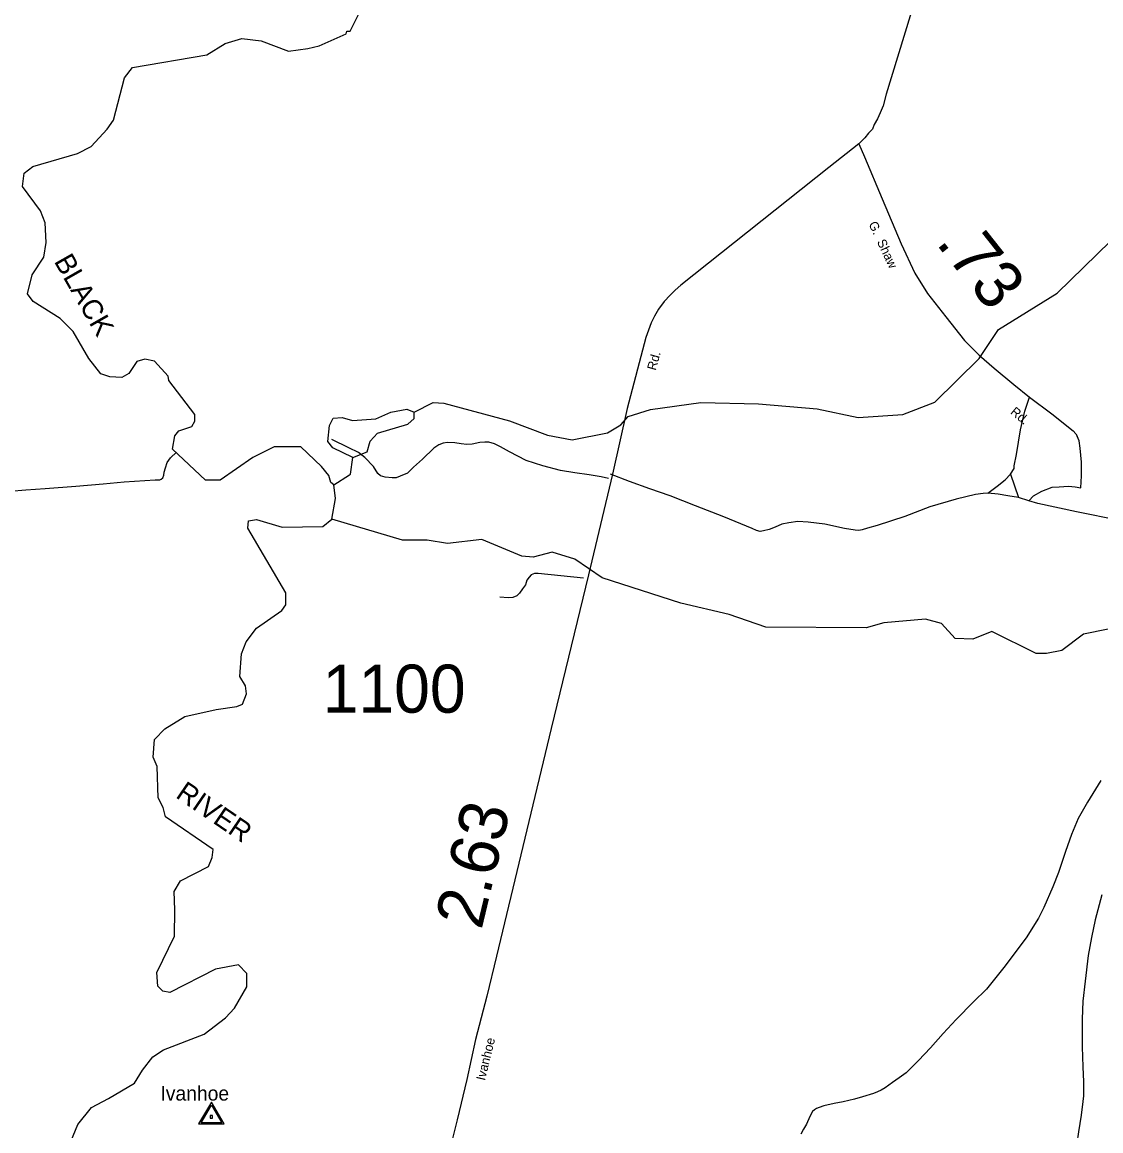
# Model space of a CAD drawing. Extents: x 2093524 to 2270757, y 289120 to 570408.
# Drawn here: x 2222555 to 2233771, y 318082 to 329610 of the extents above; entities that cross this region are included whole.
import ezdxf

# ---------------------------------------------------------------- set-up
doc = ezdxf.new("R2010")
doc.units = 0
for name, color, linetype in [('Exist Hydrographic Creek Single Shore', 7, 'Continuous'), ('Exist Hydrographic Lake Shore', 7, 'Continuous'), ('Exist Hydrographic River Shore', 7, 'Continuous'), ('Exist Hydrographic River Shore Label', 7, 'Continuous'), ('Exist Road Non-System Type 51', 7, 'Continuous'), ('Exist Road Secondary Mileage Hundredths English Label', 7, 'Continuous'), ('Exist Road Secondary Type 51 Attributed', 7, 'Continuous'), ('Exist Road Secondary Type 51 Label', 7, 'Continuous'), ('Exist Road Secondary Type 51 Number Label', 7, 'Continuous'), ('Exist Survey Geodetic Marker CELL', 7, 'Continuous'), ('Exist Survey Geodetic Marker Label', 7, 'Continuous')]:
    doc.layers.add(name, color=color, linetype=linetype)

msp = doc.modelspace()

# ---------------------------------------------------------------- linework, layer by layer
at = {"layer": 'Exist Hydrographic Creek Single Shore'}
for p, q in [((2226509, 324224), (2225774, 324441)), ((2226767, 324225), (2226509, 324224)), ((2232639, 323273), (2232440, 323195))]:
    msp.add_line(p, q, dxfattribs=at)
for points in [[(2226631, 325556), (2226830, 325657), (2226938, 325648), (2227623, 325464), (2228016, 325316), (2228274, 325268), (2228640, 325339), (2228781, 325422), (2228856, 325509), (2229088, 325583), (2229612, 325655), (2230212, 325643), (2230821, 325591), (2231246, 325501), (2231713, 325531), (2232045, 325659), (2232507, 326112), (2232705, 326414), (2233318, 326792), (2233872, 327332)], [(2225796, 324799), (2225960, 324904), (2225970, 324910), (2225994, 325083)], [(2232440, 323195), (2232256, 323201), (2232113, 323358), (2231946, 323401), (2231514, 323364), (2231331, 323312), (2230289, 323319), (2229905, 323451), (2229405, 323569), (2228586, 323832), (2228301, 324027), (2228067, 324101), (2227868, 324049), (2227751, 324058), (2227333, 324230), (2226976, 324191), (2226767, 324225)], [(2238446, 323161), (2238312, 323193), (2238104, 323168), (2238013, 323084), (2237830, 323091), (2237512, 323255), (2237370, 323287), (2236987, 323315), (2236127, 323460), (2235711, 323432), (2235536, 323504), (2235393, 323612), (2235193, 323668), (2234462, 323447), (2234163, 323269), (2233997, 323265), (2233846, 323298), (2233589, 323247), (2233365, 323078), (2233207, 323045), (2233099, 323044), (2232639, 323273)]]:
    msp.add_lwpolyline(points, dxfattribs=at)
at = {"layer": 'Exist Hydrographic Lake Shore'}
for points in [[(2225994, 325083), (2225785, 325183), (2225734, 325249), (2225749, 325416), (2225790, 325491), (2225882, 325499), (2225990, 325467), (2226232, 325485), (2226390, 325554), (2226556, 325587), (2226631, 325556)], [(2225994, 325083), (2226143, 325143), (2226175, 325254), (2226250, 325337), (2226566, 325429), (2226632, 325490), (2226631, 325556)]]:
    msp.add_lwpolyline(points, dxfattribs=at)
at = {"layer": 'Exist Hydrographic River Shore'}
for p, q in [((2225932, 329516), (2225966, 329515)), ((2225669, 324991), (2225452, 325196)), ((2224991, 324440), (2225258, 324360)), ((2225683, 324365), (2225774, 324441)), ((2225258, 324360), (2225683, 324365))]:
    msp.add_line(p, q, dxfattribs=at)
for points in [[(2225966, 329515), (2226089, 329765), (2226178, 330016), (2226273, 330601), (2226288, 330844), (2226354, 331000), (2226453, 331103), (2226652, 331129)], [(2225642, 329364), (2225924, 329490), (2225932, 329516)], [(2223590, 325915), (2223465, 325924), (2223373, 325955), (2223247, 326112), (2223086, 326394), (2222952, 326528), (2222668, 326707), (2222609, 326784), (2222658, 326983), (2222781, 327167), (2222805, 327318), (2222796, 327525), (2222745, 327650), (2222560, 327900), (2222575, 328041), (2222667, 328108), (2223132, 328243), (2223273, 328319), (2223439, 328496), (2223505, 328590), (2223618, 329030), (2223701, 329140), (2224474, 329269), (2224665, 329387), (2224840, 329439)], [(2224840, 329439), (2225040, 329415), (2225324, 329308)], [(2225324, 329308), (2225524, 329337), (2225642, 329364)], [(2223830, 326107), (2223747, 326082), (2223664, 325956), (2223590, 325915)], [(2224463, 324848), (2224120, 325169), (2224144, 325310), (2224185, 325362), (2224318, 325405), (2224351, 325463), (2224350, 325529), (2224081, 325885), (2224073, 325928), (2223930, 326085), (2223830, 326107)], [(2225452, 325196), (2225177, 325194), (2224953, 325084), (2224613, 324848), (2224463, 324848)], [(2225796, 324799), (2225763, 324825), (2225745, 324898), (2225669, 324991)], [(2225774, 324441), (2225814, 324657), (2225796, 324799)], [(2224092, 319522), (2224017, 319536), (2223967, 319586), (2223957, 319728), (2224138, 320105), (2224144, 320380), (2224135, 320570), (2224201, 320681), (2224491, 320832), (2224532, 320923), (2224540, 321008), (2224046, 321346), (2224021, 321445), (2223970, 321545), (2223959, 321870), (2223917, 321969), (2223932, 322152), (2224040, 322262), (2224247, 322389), (2224571, 322464), (2224788, 322493), (2224846, 322518), (2224887, 322625), (2224878, 322708), (2224819, 322807), (2224834, 323043), (2224883, 323167), (2224991, 323309), (2225256, 323494), (2225297, 323552), (2225296, 323677), (2224900, 324350), (2224908, 324426), (2224991, 324440)], [(2224806, 319809), (2224565, 319765), (2224092, 319522)], [(2224762, 319358), (2224891, 319578), (2224891, 319719), (2224806, 319809)], [(2223005, 317837), (2223135, 318148), (2223276, 318324), (2223454, 318418), (2223722, 318578), (2223808, 318714), (2223914, 318851), (2224023, 318926), (2224447, 319088), (2224671, 319258), (2224762, 319358)]]:
    msp.add_lwpolyline(points, dxfattribs=at)
at = {"layer": 'Exist Road Non-System Type 51'}
for p in [(2232833, 324909), (2233021, 324633)]:
    msp.add_line(p, (2232915, 324668), dxfattribs=at)
for points in [[(2232833, 324909), (2232870, 324970), (2232868, 324996), (2232893, 325116), (2232935, 325370), (2232982, 325566), (2233028, 325711)], [(2228651, 324865), (2228575, 324883), (2228449, 324902), (2228301, 324923), (2228153, 324949), (2227968, 324998), (2227794, 325054), (2227621, 325141), (2227529, 325194), (2227467, 325226), (2227409, 325243), (2227365, 325243), (2227313, 325238), (2227235, 325222), (2227179, 325219), (2227121, 325225), (2227053, 325236), (2226977, 325238), (2226933, 325233), (2226889, 325217), (2226834, 325180), (2226717, 325068), (2226625, 324983), (2226562, 324922), (2226486, 324888), (2226444, 324873), (2226402, 324873), (2226328, 324878), (2226280, 324894), (2226254, 324918), (2226207, 324989), (2226119, 325085), (2226052, 325134), (2225950, 325185), (2225775, 325270)], [(2233021, 324633), (2233071, 324684), (2233158, 324734), (2233264, 324775), (2233338, 324780), (2233434, 324784), (2233502, 324777), (2233564, 324769), (2233571, 324892), (2233568, 325035), (2233555, 325181), (2233544, 325257), (2233526, 325307)], [(2222432, 324734), (2222592, 324747), (2222796, 324763), (2223112, 324785), (2223397, 324809), (2223617, 324830), (2223831, 324846), (2223939, 324851), (2223975, 324853), (2223987, 324853), (2224001, 324857), (2224017, 324871), (2224027, 324899), (2224030, 324931), (2224044, 324977), (2224064, 325031), (2224099, 325080), (2224161, 325140)], [(2232597, 324712), (2232547, 324711), (2232467, 324699), (2232266, 324651), (2231994, 324569), (2231731, 324471), (2231446, 324376), (2231346, 324350), (2231288, 324333), (2231256, 324325), (2231215, 324329), (2231104, 324346), (2230902, 324390), (2230728, 324410), (2230620, 324418), (2230528, 324405), (2230454, 324390), (2230383, 324360), (2230323, 324335), (2230263, 324321), (2230227, 324314), (2230191, 324324), (2230145, 324344), (2229850, 324467), (2229555, 324581), (2229292, 324685), (2229080, 324757), (2228870, 324835), (2228671, 324912)], [(2232597, 324712), (2232694, 324785), (2232776, 324853), (2232833, 324909)], [(2232915, 324668), (2232803, 324685), (2232703, 324702), (2232597, 324712)], [(2234525, 324322), (2234373, 324358), (2233964, 324429), (2233518, 324517), (2233115, 324604), (2233021, 324633)], [(2228390, 323830), (2227920, 323878), (2227882, 323876), (2227846, 323863), (2227826, 323839), (2227804, 323807), (2227788, 323759), (2227759, 323717), (2227727, 323674), (2227698, 323644), (2227658, 323628), (2227608, 323625), (2227520, 323632)], [(2233771, 321726), (2233631, 321501), (2233536, 321331), (2233465, 321162), (2233403, 320986), (2233331, 320767), (2233272, 320621), (2233178, 320406), (2233123, 320294), (2232995, 320089), (2232761, 319781), (2232581, 319555), (2232448, 319423), (2232268, 319240), (2232132, 319095), (2232000, 318947), (2231875, 318812), (2231806, 318743), (2231745, 318686), (2231673, 318634), (2231606, 318585), (2231527, 318528), (2231485, 318504), (2231447, 318487), (2231406, 318471), (2231292, 318436), (2231211, 318411), (2231093, 318385), (2230999, 318366), (2230891, 318341), (2230841, 318325), (2230813, 318314), (2230792, 318300), (2230774, 318282), (2230746, 318230), (2230709, 318151), (2230678, 318101), (2230651, 318049)], [(2233782, 320537), (2233711, 320276), (2233672, 320094), (2233638, 319904), (2233608, 319640), (2233584, 319430), (2233576, 319243), (2233577, 318957), (2233584, 318747), (2233591, 318593), (2233592, 318517), (2233591, 318479), (2233589, 318447), (2233582, 318387), (2233567, 318245), (2233537, 318071), (2233521, 317955), (2233504, 317812), (2233483, 317556), (2233462, 317298), (2233450, 317158), (2233439, 317060), (2233422, 316984)]]:
    msp.add_lwpolyline(points, dxfattribs=at)
at = {"layer": 'Exist Road Secondary Type 51 Attributed'}
for points in [[(2233528, 335412), (2233278, 334619), (2231987, 330325), (2231540, 328861), (2231507, 328741), (2231475, 328668), (2231447, 328604), (2231414, 328547), (2231396, 328499), (2231356, 328455), (2231317, 328407), (2231253, 328345)], [(2231253, 328345), (2230941, 328099), (2229403, 326876), (2229346, 326824), (2229293, 326773), (2229232, 326705), (2229170, 326625), (2229131, 326554), (2229094, 326484), (2229040, 326330), (2228845, 325593), (2228694, 324909), (2228445, 323863), (2228054, 322265), (2227487, 319898), (2227386, 319484), (2227267, 319032), (2227178, 318617), (2227079, 318197), (2227007, 317907)], [(2231253, 328345), (2231315, 328210), (2231498, 327773), (2231694, 327307), (2231838, 327000), (2231968, 326790), (2232160, 326547), (2232354, 326299), (2232505, 326146), (2232660, 326014), (2232867, 325841), (2233028, 325711), (2233260, 325539), (2233483, 325361), (2233509, 325331), (2233526, 325307)]]:
    msp.add_lwpolyline(points, dxfattribs=at)
at = {"layer": 'Exist Survey Geodetic Marker CELL'}
for points in [[(2224657, 318155), (2224523, 318381), (2224389, 318155)], [(2224631, 318167), (2224415, 318167), (2224523, 318350)], [(2224535, 318214), (2224535, 318242), (2224511, 318242), (2224511, 318214)]]:
    msp.add_lwpolyline(points, close=True, dxfattribs=at)

# ---------------------------------------------------------------- texts
at = {"layer": 'Exist Hydrographic River Shore Label'}
for s, rotation, p in [('BLACK', 299.7224, (2222882, 327124)), ('RIVER', 325.636, (2224141, 321555))]:
    msp.add_text(s, height=210, rotation=rotation, dxfattribs=at).set_placement(p)
at = {"layer": 'Exist Road Secondary Mileage Hundredths English Label'}
for s, rotation, p in [('.73', 308.4009, (2232048, 327313)), ('2.63', 76.5217, (2227330, 320164))]:
    msp.add_text(s, height=500, rotation=rotation, dxfattribs=at).set_placement(p)
at = {"layer": 'Exist Road Secondary Type 51 Label'}
for s, rotation, p in [('G.  Shaw', 295.2104, (2231353, 327512)), ('Rd.', 74.4368, (2229142, 325983)), ('Rd.', 320.2409, (2232823, 325545)), ('Ivanhoe', 76.2234, (2227366, 318599))]:
    msp.add_text(s, height=95, rotation=rotation, dxfattribs=at).set_placement(p)
at = {"layer": 'Exist Road Secondary Type 51 Number Label'}
msp.add_text('1100', height=500, dxfattribs=at).set_placement((2225679, 322430))
at = {"layer": 'Exist Survey Geodetic Marker Label'}
msp.add_text('Ivanhoe', height=150, dxfattribs=at).set_placement((2223993, 318397))

doc.saveas('drawing.dxf')
